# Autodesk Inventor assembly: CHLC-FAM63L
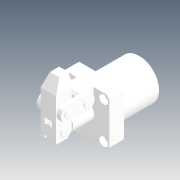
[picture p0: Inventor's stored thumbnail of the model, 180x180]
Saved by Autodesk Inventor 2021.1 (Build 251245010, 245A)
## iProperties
Created: 2019-04
Part Number: CHLC-FAM63L
Description: STEP AP214
Document SubType Name: Assembly
Designer: user
Title: CHLC-FAM63L.STEP
Revision Number: ÈÎºÎ
Sending System: SolidWorks 2016
Preprocessor: SwSTEP 2.0
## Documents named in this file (10)
- D:\Vault_2016\Projekty\Clamptek\Hydraulic\CHLC\CHLC-63\Inventor\CHLC-FAM63L\CHLC-FAM63L.iam
- D:\Vault_2016\Projekty\Clamptek\Hydraulic\CHLC\CHLC-63\Inventor\CHLC-FAM63L\benti.ipt
- D:\Vault_2016\Projekty\Clamptek\Hydraulic\CHLC\CHLC-63\Inventor\CHLC-FAM63L\CHLC-63-01.ipt
- D:\Vault_2016\Projekty\Clamptek\Hydraulic\CHLC\CHLC-63\Inventor\CHLC-FAM63L\CHLC-63-02.ipt
- D:\Vault_2016\Projekty\Clamptek\Hydraulic\CHLC\CHLC-63\Inventor\CHLC-FAM63L\CHLC-63-03.ipt
- D:\Vault_2016\Projekty\Clamptek\Hydraulic\CHLC\CHLC-63\Inventor\CHLC-FAM63L\CHLC-63-04.ipt
- D:\Vault_2016\Projekty\Clamptek\Hydraulic\CHLC\CHLC-63\Inventor\CHLC-FAM63L\CHLC-63-05.ipt
- D:\Vault_2016\Projekty\Clamptek\Hydraulic\CHLC\CHLC-63\Inventor\CHLC-FAM63L\CHLC-63-07.ipt
- D:\Vault_2016\Projekty\Clamptek\Hydraulic\CHLC\CHLC-63\Inventor\CHLC-FAM63L\socket set screw flat point_iso_ISO 4026 - M5 x 6-S.ipt
- D:\Vault_2016\Projekty\Clamptek\Hydraulic\CHLC\CHLC-63\Inventor\CHLC-FAM63L\YAKUAI.ipt
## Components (19 placed, 19 different names)
1. benti_1
2. CHLC-63-01_2
3. CHLC-63-02_3
4. CHLC-63-03_4
5. CHLC-63-04_5
6. CHLC-63-05_6
7. CHLC-63-07_7
8. socket set screw flat point_iso_ISO 4026 - M5 x 6-S_8
9. YAKUAI_9
10. CHLC-63-04_10
11. CHLC-63-07_11
12. CHLC-63-07_12
13. CHLC-63-07_13
14. CHLC-63-07_14
15. CHLC-63-07_15
16. CHLC-63-03_16
17. socket set screw flat point_iso_ISO 4026 - M5 x 6-S_17
18. socket set screw flat point_iso_ISO 4026 - M5 x 6-S_18
19. socket set screw flat point_iso_ISO 4026 - M5 x 6-S_19
